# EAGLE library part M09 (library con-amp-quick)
AMP QUICK CONNECTOR
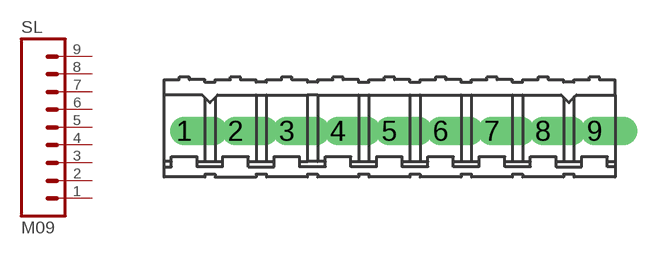
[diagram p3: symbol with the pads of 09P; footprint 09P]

Designator prefix SL

## M09  [09P]
1  1  pas
2  2  pas
3  3  pas
4  4  pas
5  5  pas
6  6  pas
7  7  pas
8  8  pas
9  9  pas

## Footprint 09P (pad centres in mm)
AMP QUICK CONNECTOR
drill 0.914 offset: 1 -10.16,0; 2 -7.62,0; 3 -5.08,0; 4 -2.54,0; 5 0,0; 6 2.54,0; 7 5.08,0; 8 7.62,0; 9 10.16,0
